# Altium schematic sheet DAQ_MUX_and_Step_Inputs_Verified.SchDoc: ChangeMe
size 558 x 431 mm; Date: Not shown in title block; ApprovedBy: Not shown in title block; CheckedBy: Not shown in title block; Author: Not shown in title block; CompanyName: Not shown in title block; DrawnBy: Not shown in title block; Engineer: Not shown in title block; Organization: Not shown in title block; Address1: Not shown in title block; Address2: Not shown in title block; Address3: Not shown in title block; Address4: Not shown in title block; DocumentNumber: 1; Revision: Use project parameter SCH_Rev; SheetNumber: 1; SheetTotal: 1; PageSetup: Record=PageOptions|CenterHorizontal=True|CenterVertical=True|PrintScale=1.00|XCorrection=1.00|YCorrection=1.00|PrintKind=0|BorderSize=5000000|LeftOffset=0|BottomOffset=0|Orientation=2|PaperLength=1000|PaperWidth=1000|Scale=100|PaperSource=15|PrintQuality=600|MediaType=1|DitherType=10|PaperKind=Letter|PrintScaleMode=1
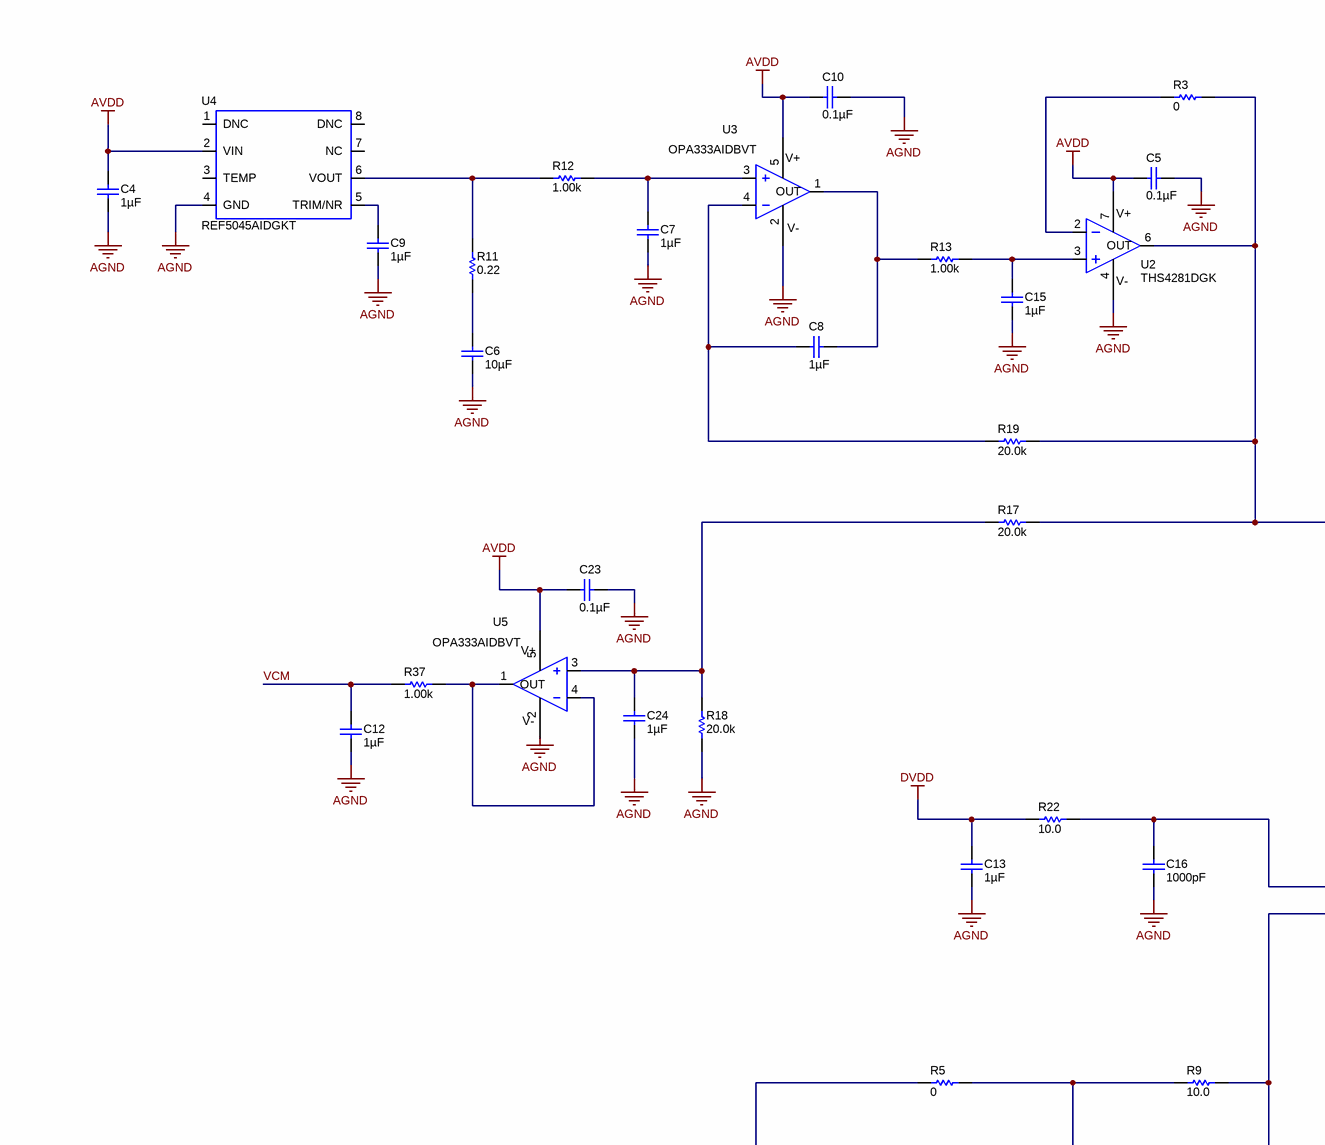
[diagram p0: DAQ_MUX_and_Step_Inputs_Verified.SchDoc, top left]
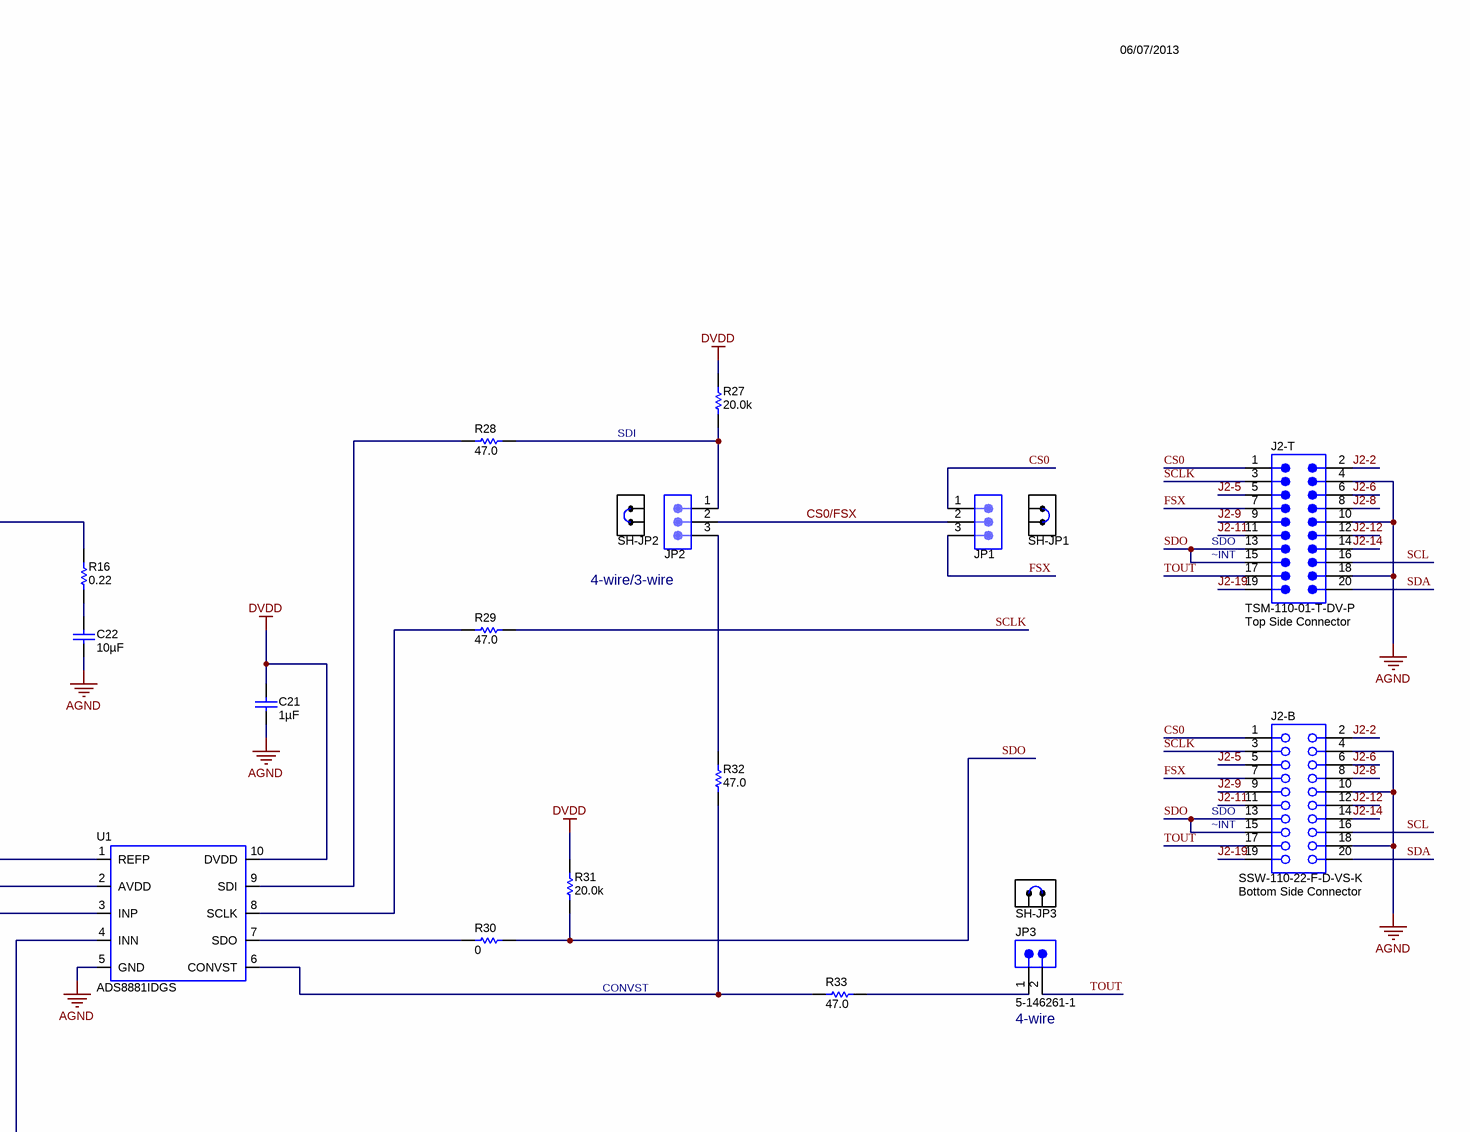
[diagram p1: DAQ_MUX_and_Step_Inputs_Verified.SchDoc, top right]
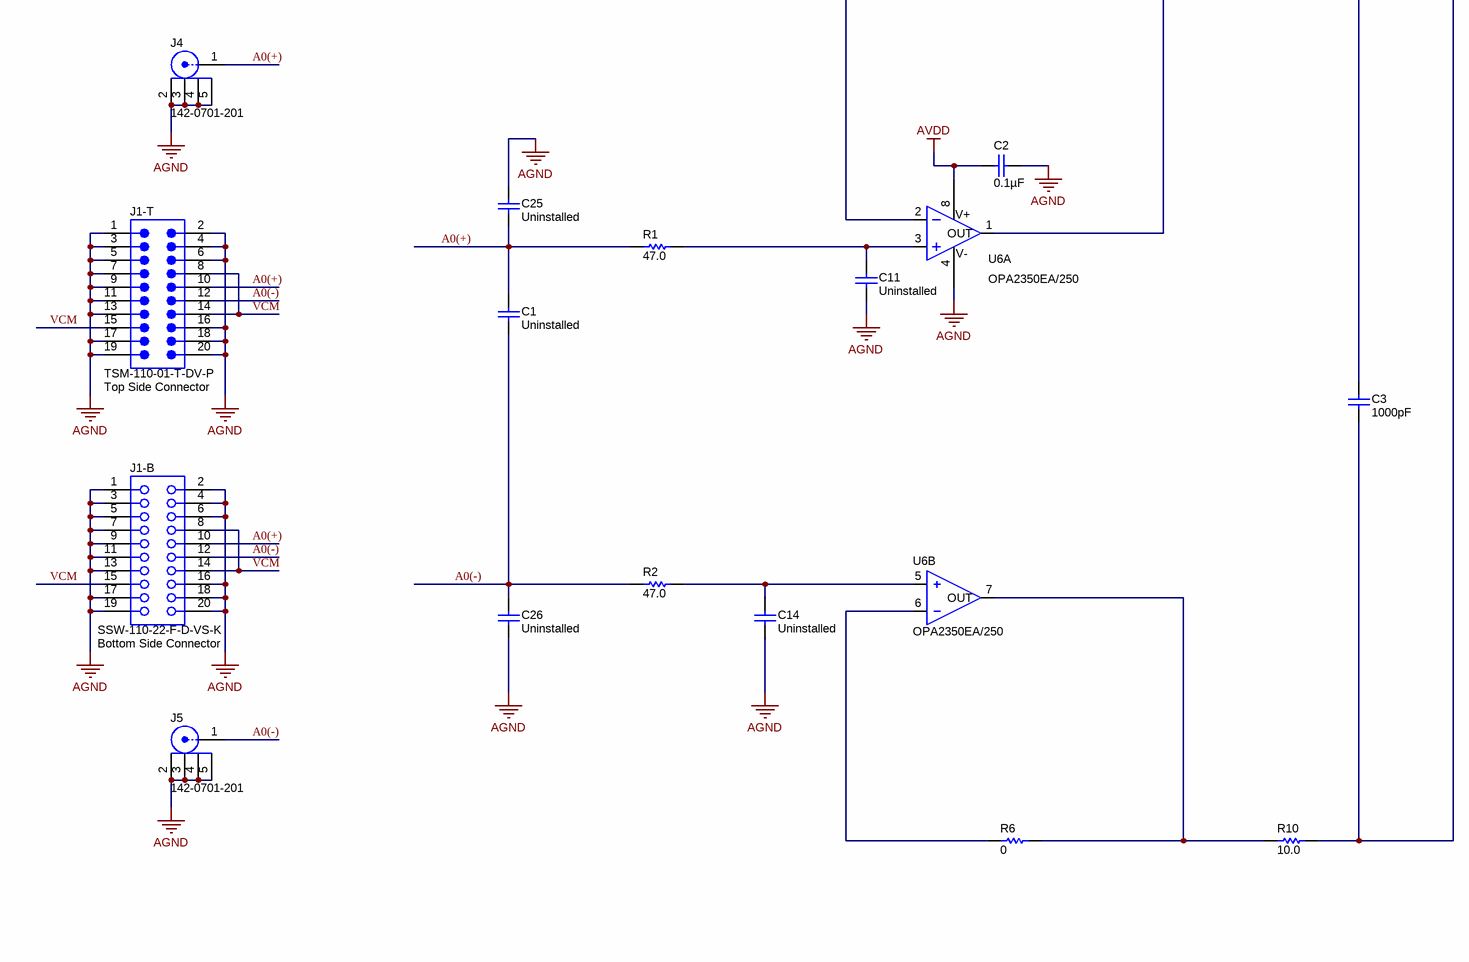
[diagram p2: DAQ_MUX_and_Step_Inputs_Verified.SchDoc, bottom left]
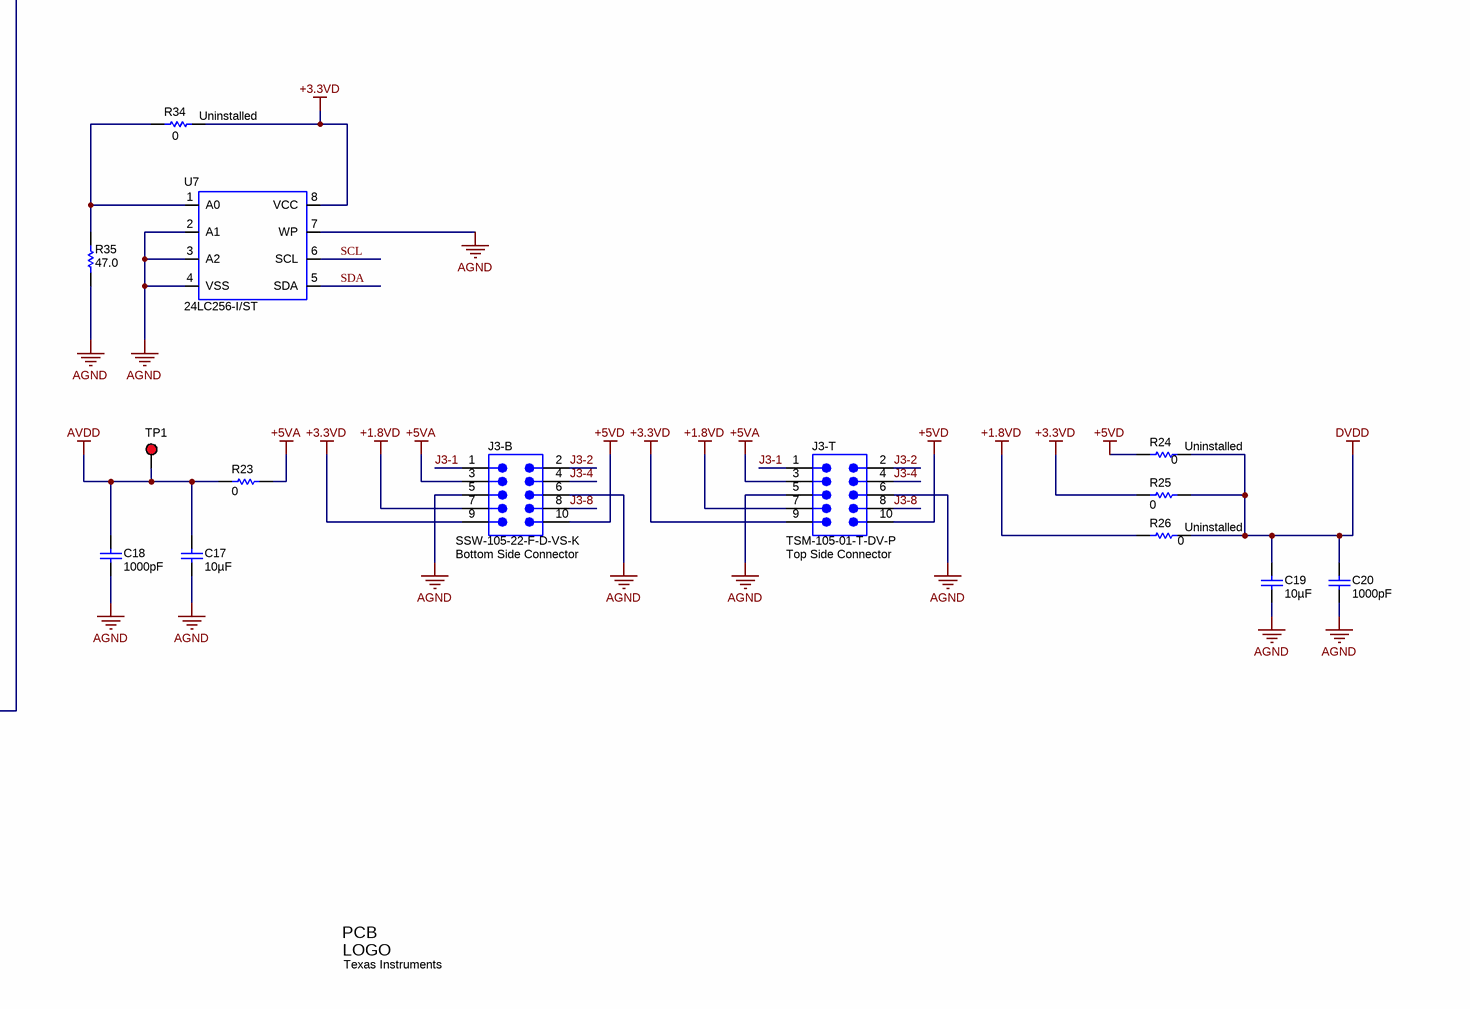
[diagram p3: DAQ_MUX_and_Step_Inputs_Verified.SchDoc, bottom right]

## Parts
C1  N/A  [0603]  (value not drawn)
C2  ValueDisplayed: 0.1µF  [0603]  (hidden comment: 06033C104KAT2A)
C3  ValueDisplayed: 1000pF  [0603]  (hidden comment: C0603C102J5GAC)
C4  ValueDisplayed: 1µF  [0603]  (hidden comment: GRM188R71A105KA61D)
C5  ValueDisplayed: 0.1µF  [0603]  (hidden comment: 06033C104KAT2A)
C6  ValueDisplayed: 10µF  [0805]  (hidden comment: GRM21BR71A106KE51L)
C7  ValueDisplayed: 1µF  [0603]  (hidden comment: GRM188R71A105KA61D)
C8  ValueDisplayed: 1µF  [0603]  (hidden comment: GRM188R71A105KA61D)
C9  ValueDisplayed: 1µF  [0603]  (hidden comment: GRM188R71A105KA61D)
C10  ValueDisplayed: 0.1µF  [0603]  (hidden comment: 06033C104KAT2A)
C11  N/A  [0603]  (value not drawn)
C12  ValueDisplayed: 1µF  [0603]  (hidden comment: GRM188R71A105KA61D)
C13  ValueDisplayed: 1µF  [0603]  (hidden comment: GRM188R71A105KA61D)
C14  N/A  [0603]  (value not drawn)
C15  ValueDisplayed: 1µF  [0603]  (hidden comment: GRM188R71A105KA61D)
C16  ValueDisplayed: 1000pF  [0603]  (hidden comment: C0603C102J5GAC)
C17  ValueDisplayed: 10µF  [1206]  (hidden comment: GRM31CR71C106KAC7L)
C18  ValueDisplayed: 1000pF  [0603]  (hidden comment: C0603C102J5GAC)
C19  ValueDisplayed: 10µF  [1206]  (hidden comment: GRM31CR71C106KAC7L)
C20  ValueDisplayed: 1000pF  [0603]  (hidden comment: C0603C102J5GAC)
C21  ValueDisplayed: 1µF  [0603]  (hidden comment: GRM188R71A105KA61D)
C22  ValueDisplayed: 10µF  [0805]  (hidden comment: GRM21BR71A106KE51L)
C23  ValueDisplayed: 0.1µF  [0603]  (hidden comment: 06033C104KAT2A)
C24  ValueDisplayed: 1µF  [0603]  (hidden comment: GRM188R71A105KA61D)
C25  N/A  [0603]  (value not drawn)
C26  N/A  [0603]  (value not drawn)
J1-B  Bottom Side Connector  [CONN_SSW-110-22-F-D-VS-K]
J1-T  TSM-110-01-T-DV-P  Comment_1: Top Side Connector  [CONN_TSM-110-01-T-DV-P]
J2-B  Bottom Side Connector  [CONN_SSW-110-22-F-D-VS-K]
J2-T  TSM-110-01-T-DV-P  Comment_1: Top Side Connector  [CONN_TSM-110-01-T-DV-P]
J3-B  SSW-105-22-F-D-VS-K  Comment_1: Bottom Side Connector  [CONN_SSW-105-22-F-D-VS-K]
J3-T  TSM-105-01-T-DV-P  Comment_1: Top Side Connector  [CONN_TSM-105-01-T-DV-P]
J4  142-0701-201  [Johnson_142-0701-20x]
J5  142-0701-201  [Johnson_142-0701-20x]
JP1  PBC03SAAN  [PBC03SAAN]  (value not drawn)
JP2  PBC03SAAN  [PBC03SAAN]  (value not drawn)
JP3  5-146261-1  [CONN_5-146261-1]
Logo1  Texas Instruments  [TIBUG2-NEW]  (no BOM)
R1  value 47.0  [0603]  (hidden comment: RC0603FR-0747RL)
R2  value 47.0  [0603]  (hidden comment: RC0603FR-0747RL)
R3  value 0  [0603]  (hidden comment: ERJ-3GEY0R00V)
R5  value 0  [0603]  (hidden comment: ERJ-3GEY0R00V)
R6  value 0  [0603]  (hidden comment: ERJ-3GEY0R00V)
R9  value 10.0  [0603]  (hidden comment: CRCW060310R0FKEA)
R10  value 10.0  [0603]  (hidden comment: CRCW060310R0FKEA)
R11  value 0.22  [0603]  (hidden comment: ERJ-3RQFR22V)
R12  value 1.00k  [0603]  (hidden comment: CRCW06031K00FKEA)
R13  value 1.00k  [0603]  (hidden comment: CRCW06031K00FKEA)
R16  value 0.22  [0603]  (hidden comment: ERJ-3RQFR22V)
R17  value 20.0k  [0603]  (hidden comment: CRCW060320K0FKEA)
R18  value 20.0k  [0603]  (hidden comment: CRCW060320K0FKEA)
R19  value 20.0k  [0603]  (hidden comment: CRCW060320K0FKEA)
R22  value 10.0  [0603]  (hidden comment: CRCW060310R0FKEA)
R23  value 0  [0603]  (hidden comment: ERJ-3GEY0R00V)
R24  Comment_2: 0  [0603]  (hidden comment: Uninstalled)
R25  value 0  [0603]  (hidden comment: ERJ-3GEY0R00V)
R26  Uninstalled  Comment_1: 0  [0603]
R27  value 20.0k  [0603]  (hidden comment: CRCW060320K0FKEA)
R28  value 47.0  [0603]  (hidden comment: RC0603FR-0747RL)
R29  value 47.0  [0603]  (hidden comment: RC0603FR-0747RL)
R30  value 0  [0603]  (hidden comment: ERJ-3GEY0R00V)
R31  value 20.0k  [0603]  (hidden comment: CRCW060320K0FKEA)
R32  value 47.0  [0603]  (hidden comment: RC0603FR-0747RL)
R33  value 47.0  [0603]  (hidden comment: RC0603FR-0747RL)
R34  Comment_2: 0  [0603]  (hidden comment: Uninstalled)
R35  value 47.0  [0603]  (hidden comment: RC0603FR-0747RL)
R37  value 1.00k  [0603]  (hidden comment: CRCW06031K00FKEA)
SH-JP1  969102-0000-DA  [SNT-100-BK-G]  (value not drawn)
SH-JP2  969102-0000-DA  [SNT-100-BK-G]  (value not drawn)
SH-JP3  969102-0000-DA  [SNT-100-BK-G]  (value not drawn)
TP1  5000  [Keystone5000]  (value not drawn)
U1  ADS8881IDGS  [DGS-10]
U2  THS4281DGK  [DGK-8]
U3  OPA333AIDBVT  [DBV-5]
U4  REF5045AIDGKT  [DGK-8]
U5  OPA333AIDBVT  [DBV-5]
U6  OPA2350EA/250  [DGK-8]  (parts A,B of 2)
U7  24LC256-I/ST  [TSSOP-8]

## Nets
+1.8VD: J3-B.7 J3-T.7 R26.1
+3.3VD: J3-B.9 J3-T.9 R25.1 R34.2 U7.8(VCC)
+5VA: J3-B.3 J3-T.3 R23.2
+5VD: J3-B.10 J3-T.10 R24.1
AGND: C2.2 C4.1 C5.2 C6.2 C7.1 C9.1 C10.2 C11.1 C12.1 C13.1 C14.1 C15.1 C16.1 C17.2 C18.1 C19.2 C20.1 C21.1 C22.2 C23.2 C24.1 C25.1 C26.1 J1-B.1 J1-B.2 J1-B.3 J1-B.4 J1-B.5 J1-B.6 J1-B.7 J1-B.9 J1-B.11 J1-B.13 J1-B.16 J1-B.17 J1-B.18 J1-B.19 J1-B.20 J1-T.1 J1-T.2 J1-T.3 J1-T.4 J1-T.5 J1-T.6 J1-T.7 J1-T.9 J1-T.11 J1-T.13 J1-T.16 J1-T.17 J1-T.18 J1-T.19 J1-T.20 J2-B.4 J2-B.10 J2-B.18 J2-T.4 J2-T.10 J2-T.18 J3-B.5 J3-B.6 J3-T.5 J3-T.6 J4.2 J4.3 J4.4 J4.5 J5.2 J5.3 J5.4 J5.5 R18.2 R35.2 U1.5(GND) U2.4(V-) U3.2(V-) U4.4(GND) U5.2(V-) U6.4(V-) U7.2(A1) U7.3(A2) U7.4(VSS) U7.7(WP)
AVDD: C2.1 C4.2 C5.1 C10.1 C17.1 C18.2 C23.1 R23.1 TP1.1 U2.7(V+) U3.5(V+) U4.2(VIN) U5.5(V+) U6.8(V+)
DVDD: C13.2 C19.1 C20.2 C21.2 R22.1 R24.2 R25.2 R26.2 R27.1 R31.1 U1.10(DVDD)
A0(+): C1.2 C25.2 J1-B.10 J1-T.10 J4.1 R1.2
A0(-): C1.1 C26.2 J1-B.12 J1-T.12 J5.1 R2.2
CS0: J2-B.1 J2-T.1 JP1.1
CS0/FSX: JP1.2 JP2.2
FSX: J2-B.7 J2-T.7 JP1.3
J2-2: J2-B.2 J2-T.2
J2-5: J2-B.5 J2-T.5
J2-6: J2-B.6 J2-T.6
J2-8: J2-B.8 J2-T.8
J2-9: J2-B.9 J2-T.9
J2-11: J2-B.11 J2-T.11
J2-12: J2-B.12 J2-T.12
J2-14: J2-B.14 J2-T.14
J2-19: J2-B.19 J2-T.19
J3-1: J3-B.1 J3-T.1
J3-2: J3-B.2 J3-T.2
J3-4: J3-B.4 J3-T.4
J3-8: J3-B.8 J3-T.8
SCL: J2-B.16 J2-T.16 U7.6(SCL)
SCLK: J2-B.3 J2-T.3 R29.2
SDA: J2-B.20 J2-T.20 U7.5(SDA)
SDO: J2-B.13 J2-B.15 J2-T.13 J2-T.15 R30.2 R31.2
TOUT: J2-B.17 J2-T.17 JP3.2
VCM: C12.2 J1-B.8 J1-B.14 J1-B.15 J1-T.8 J1-T.14 J1-T.15 R37.2
NetC3_1: C3.1 R10.2 U1.4(INN)
NetC3_2: C3.2 R9.2 U1.3(INP)
NetC6_1: C6.1 R11.2
NetC7_2: C7.2 R12.2 U3.3
NetC8_1: C8.1 R19.1 U3.4
NetC8_2: C8.2 R13.1 U3.1(OUT)
NetC9_2: C9.2 U4.5(TRIM/NR)
NetC11_2: C11.2 R1.1 U6.3
NetC14_2: C14.2 R2.1 U6.5
NetC15_2: C15.2 R13.2 U2.3(+)
NetC16_2: C16.2 R22.2 U1.2(AVDD)
NetC22_1: C22.1 R16.2
NetC24_2: C24.2 R17.1 R18.1 U5.3
NetJP2_1: JP2.1 R27.2 R28.2
NetJP2_3: JP2.3 R32.2
NetJP3_1: JP3.1 R33.2
NetR3_1: R3.1 U2.2(-)
NetR3_2: R3.2 R16.1 R17.2 R19.2 U1.1(REFP) U2.6(OUT)
NetR5_1: R5.1 U6.2
NetR5_2: R5.2 R9.1 U6.1(OUT)
NetR6_1: R6.1 U6.6
NetR6_2: R6.2 R10.1 U6.7(OUT)
NetR11_1: R11.1 R12.1 U4.6(VOUT)
NetR28_1: R28.1 U1.9(SDI)
NetR29_1: R29.1 U1.8(SCLK)
NetR30_1: R30.1 U1.7(SDO)
NetR32_1: R32.1 R33.1 U1.6(CONVST)
NetR34_1: R34.1 R35.1 U7.1(A0)
NetR37_1: R37.1 U5.1(OUT) U5.4

Not connected (* = marked no-connect by the designer): U4 1(DNC) 3(TEMP) 7(NC) 8(DNC)

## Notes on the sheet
- 06/07/2013
- SDI
- 4-wire/3-wire
- (near J2-T) SDO
- (near J2-T) ~INT
- (near J2-B) SDO
- (near J2-B) ~INT
- CONVST
- (near JP3) 4-wire

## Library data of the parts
C1 C11 C14 C25 C26 = 06033C104KAT2A: Uninstalled; Polarized: N; CompType: Capacitor; U/M: EA; VDC_V: 25; TempCo: X7R
C2 C5 C10 C23 = 06033C104KAT2A: CAP, CERM, 0.1uF, 25V, +/-10%, X7R, 0603; Manufacturer: AVX; Polarized: N; CompType: Capacitor; U/M: EA; Cap_F: 0.0000001; Tolerance_%: 10; ESR_Ohm: 0.05; Value1: 0.05 ohm; VDC_V: 25; TaMin_C: -55; TaMax_C: 125
C3 C16 C18 C20 = C0603C102J5GAC: CAP, CERM, 1000pF, 50V, +/-5%, C0G/NP0, 0603; Manufacturer: Kemet; Polarized: N; CompType: Capacitor; U/M: EA; Cap_F: 0.000000001; Tolerance_%: 5; Value1: Unknown; VDC_V: 50; TaMin_C: -55; TaMax_C: 125
C4 C7-C9 C12 C13 C15 C21 C24 = GRM188R71A105KA61D: CAP, CERM, 1uF, 10V, +/-10%, X7R, 0603; Manufacturer: MuRata; Polarized: N; CompType: Capacitor; U/M: EA; Cap_F: 0.000001; Tolerance_%: 10; ESR_Ohm: 0.011; Value1: 0.011 ohm; TaMin_C: -55; TaMax_C: 125
C6 C22 = GRM21BR71A106KE51L: CAP, CERM, 10uF, 10V, +/-10%, X7R, 0805; Manufacturer: MuRata; Polarized: N; CompType: Capacitor; U/M: EA; Cap_F: 0.00001; Tolerance_%: 10; ESR_Ohm: 0.003; Value1: 0.003 ohm; TaMin_C: -55; TaMax_C: 125
C17 C19 = GRM31CR71C106KAC7L: CAP, CERM, 10uF, 16V, +/-10%, X7R, 1206; Manufacturer: MuRata; Polarized: N; CompType: Capacitor; U/M: EA; Cap_F: 0.00001; Tolerance_%: 10; Value1: Unknown; VDC_V: 16; TaMin_C: -55; TaMax_C: 125
J1-B J2-B = SSW-110-22-F-D-VS-K: Connector, Receptacle, 100mil, 10x2, Gold plated, SMD; Manufacturer: Samtec, Inc.; SymbolCreator: a0412235; U/M: EA
J1-T J2-T = TSM-110-01-T-DV-P: Header, 100mil, 10x2, SMD; Manufacturer: Samtec, Inc.; SymbolCreator: a0412235; CompType: Connector; U/M: EA
J3-B = SSW-105-22-F-D-VS-K: Connector, Header, 10-Pos (10x2), Receptacle, 100x100-mil Pitch; Manufacturer: Samtec, Inc.; SymbolCreator: a0412235; U/M: EA
J3-T = TSM-105-01-T-DV-P: Header, 100mil, 5x2, SMD; Manufacturer: Samtec, Inc.; SymbolCreator: a0412235; CompType: Connector; U/M: EA
J4 J5 = 142-0701-201: Connector, TH, SMA; Manufacturer: Emerson Network Power; U/M: EA
JP1 JP2 = PBC03SAAN: Header, TH, 100mil, 1x3, Gold plated, 230 mil above insulator; Manufacturer: Sullins Connector Solutions; U/M: EA
JP3 = 5-146261-1: Header, 100mil, 2x1, Gold plated, TH; Manufacturer: TE Connectivity; SymbolCreator: a0412235; U/M: EA
Logo1 = TI_Logo: Texas Instrument Corporate Signature; SymbolCreator: codlsc
R1 R2 R28 R29 R32 R33 R35 = RC0603FR-0747RL: RES, 47.0 ohm, 1%, 0.1W, 0603; Manufacturer: Yageo America; CompType: Resistor; Res_ohm: 47; Value_Code: 47R0; Tolerance_%: 1; Power_W: 0.1; VDC_V: 150; TempCo: 200 ppm/C; U/M: EA
R3 R5 R6 R23 R25 R30 = ERJ-3GEY0R00V: RES, 0 ohm, 5%, 0.1W, 0603; Manufacturer: Panasonic; CompType: Resistor; Value_Code: 0000; Tolerance_%: 5; Power_W: 0.1; VDC_V: 50; TempCo: 600 ppm/C; EIA_Code: E24; U/M: EA
R9 R10 R22 = CRCW060310R0FKEA: RES, 10.0 ohm, 1%, 0.1W, 0603; Manufacturer: Vishay-Dale; CompType: Resistor; Res_ohm: 10; Value_Code: 10R0; Tolerance_%: 1; Power_W: 0.1; VDC_V: 75; TempCo: 100 ppm/C; EIA_Code: E96; U/M: EA
R11 R16 = ERJ-3RQFR22V: RES, 0.22 ohm, 1%, 0.1W, 0603; Manufacturer: Panasonic; CompType: Resistor; Value_Code: R220; Tolerance_%: 1; Power_W: 0.1; TempCo: 300 ppm/C; EIA_Code: E96; U/M: EA
R12 R13 R37 = CRCW06031K00FKEA: RES, 1.00k ohm, 1%, 0.1W, 0603; Manufacturer: Vishay-Dale; CompType: Resistor; Res_ohm: 1000; Value_Code: 1k00; Tolerance_%: 1; Power_W: 0.1; VDC_V: 75; TempCo: 100 ppm/C; EIA_Code: E96; U/M: EA
R17-R19 R27 R31 = CRCW060320K0FKEA: RES, 20.0k ohm, 1%, 0.1W, 0603; Manufacturer: Vishay-Dale; CompType: Resistor; Res_ohm: 20000; Value_Code: 20k0; Tolerance_%: 1; Power_W: 0.1; VDC_V: 75; TempCo: 100 ppm/C; EIA_Code: E96; U/M: EA
R24 R26 R34 = ERJ-3GEY0R00V: CompType: Resistor; Value_Code: 0000; Tolerance_%: 5; Value1: 5%; Power_W: 0.1; Value2: 0.1W; VDC_V: 50; TempCo: 600 ppm/C; EIA_Code: E24; U/M: EA
SH-JP1-SH-JP3 = 969102-0000-DA: Shunt, 100mil, Gold plated, Black; Manufacturer: 3M; Alternate Manufacturer: Samtec; Value: 1x2; Note: You can "mate" this to a header by matching the designator.  i.e. use SH-J3 for header J3
TP1 = 5000: Test Point, Miniature, Red, TH; Manufacturer: Keystone; CompType: Test Point Loop; U/M: EA
U1 = ADS8881IDGS: ADC 1MSPS 18bit Fully-Diff MSOP-10; Manufacturer: Texas Instruments; SymbolCreator: a0872359; U/M: EA
U2 = THS4281DGK: IC OpAmp GP R-R 90MHz SGL MSOP-8; Manufacturer: Texas Instruments; SymbolCreator: a0872359; U/M: EA
U3 U5 = OPA333AIDBVT: OpAmp, Low Power, Low Drift, 1.8V; Manufacturer: Texas Instruments; SymbolCreator: a0872359; CompType: IC; U/M: EA
U4 = REF5045IDGK: VREF PREC 4.5V MSOP-8; Manufacturer: Texas Instruments; SymbolCreator: a0872359; CompType: IC; U/M: EA
U6 = OPA2350EA: Manufacturer: Texas Instruments; SymbolCreator: a0872359; CompType: IC; U/M: EA
U7 = 24LC256-I/ST: Manufacturer: Microchip; SymbolCreator: a0872359; CompType: EEPROM; U/M: EA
